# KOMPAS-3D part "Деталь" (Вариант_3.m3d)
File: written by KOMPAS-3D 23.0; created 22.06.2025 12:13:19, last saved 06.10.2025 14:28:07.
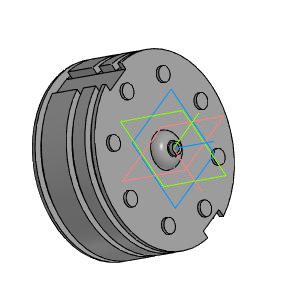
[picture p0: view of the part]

Document properties: Автор: admin; Организация: MGTU; Полное имя файла: C:\Users\ssafo\OneDrive\Desktop\ЦД_Грант\Решенные варианты\Вариант_3.m3d

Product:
- Part/product: Деталь
    Масса: 2.195385

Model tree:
1. Эскиз:1
2. Элемент вращения:1
     Угол 1 = 360
3. Эскиз:2  (with: Элемент вращения:1)
4. Элемент выдавливания:1  (with: Элемент вращения:1)
     Расстояние 2 = 45
5. Эскиз:3  (with: Элемент вращения:1)
6. Элемент выдавливания:2
     Расстояние 1 = 3
7. Эскиз:4  (with: Элемент выдавливания:2)
8. Элемент выдавливания:3
9. Фаска:1  (with: Элемент выдавливания:3)
     Угол = 45; Длина 1 = 1; Длина 2 = 1
10. Эскиз:8  (with: Элемент вращения:1)
11. Элемент выдавливания:9
     Расстояние 1 = 2
12. Массив по концентрической сетке:2  (with: Элемент выдавливания:9, Элемент вращения:1)  (8 pattern instances)
     Шаг 2 = 360
13. Эскиз:9  (with: Элемент вращения:1)
14. Элемент выдавливания:10  (with: Элемент вращения:1)
     Расстояние 2 = 48
15. Скругление:1  (with: Элемент вращения:1)
     Радиус = 5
